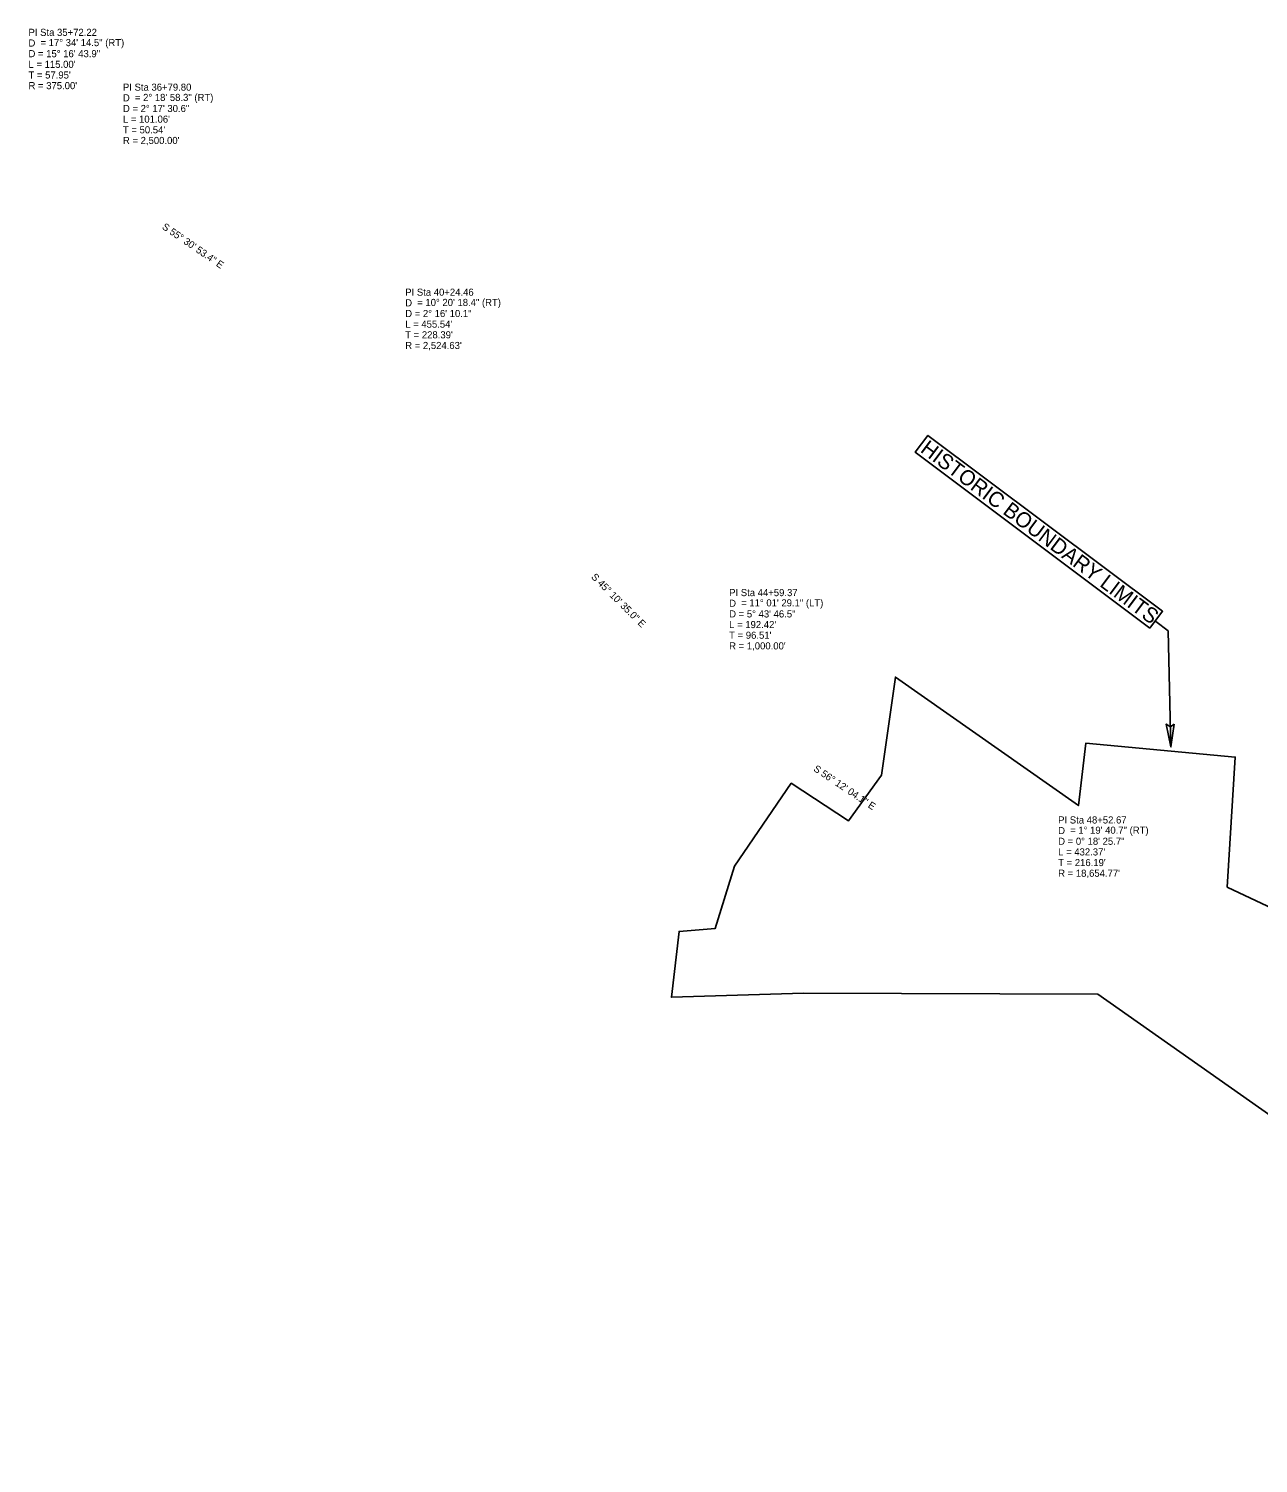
# Model space of a CAD drawing. Extents: x 928111 to 937215, y 684220 to 686530.
# Drawn here: x 930389 to 931600, y 684346 to 685759 of the extents above; entities that cross this region are included whole.
import ezdxf

# ---------------------------------------------------------------- set-up
doc = ezdxf.new("R2010")
doc.units = 0
for name, color, linetype in [('Default', 7, 'Continuous'), ('Exist Boundary Study Area', 7, 'Continuous'), ('Exist Horizontal Alignment Curve and Spiral Data', 7, 'Continuous'), ('Exist Horizontal Alignment Direction Label', 7, 'Continuous'), ('Prop DSN Text', 7, 'Continuous'), ('Prop Terminator CELL', 7, 'Continuous')]:
    doc.layers.add(name, color=color, linetype=linetype)

msp = doc.modelspace()

# ---------------------------------------------------------------- linework, layer by layer
at = {"layer": 'Default'}
for p in [(931499.2, 685174.9), (931514, 685051.5)]:
    msp.add_line(p, (931511.2, 685165.9), dxfattribs=at)
at = {"layer": 'Exist Boundary Study Area'}
msp.add_line((931442, 684808), (931152.3, 684808.7), dxfattribs=at)
for points in [[(931152.3, 684808.7), (931022.2, 684804.8), (931029.7, 684869.7), (931065.2, 684872.4), (931084.2, 684934.1), (931140.1, 685015.7), (931196.4, 684978.6), (931229.1, 685023.5), (931242.7, 685120.3), (931423, 684993.6), (931430.3, 685055.2), (931577.4, 685041.4), (931569.5, 684913.3)], [(931569.5, 684913.3), (931710.3, 684847), (931702.7, 684740.2), (931829.1, 684705.8), (931835.5, 684743.3), (931898.9, 684732.5), (931896.5, 684661.1), (932099.1, 684574.6), (932098.6, 684568.5), (932142, 684565.5), (932141, 684450.3), (932064.1, 684481.2), (932004.9, 684345.6), (931868, 684395.4), (931860.2, 684382.6), (931798.1, 684423.5), (931808.3, 684438.3), (931798.3, 684445.3), (931851.3, 684519.9), (931442, 684808)]]:
    msp.add_lwpolyline(points, dxfattribs=at)
at = {"layer": 'Prop DSN Text'}
msp.add_lwpolyline([(931493.4, 685168.6), (931262.3, 685341.8), (931274.7, 685358.4), (931505.8, 685185.2)], close=True, dxfattribs=at)
at = {"layer": 'Prop Terminator CELL'}
msp.add_lwpolyline([(931517.3, 685074), (931514, 685051.5), (931509.5, 685074), (931513.5, 685071.2)], close=True, dxfattribs=at)

# ---------------------------------------------------------------- texts
at = {"layer": 'Exist Horizontal Alignment Curve and Spiral Data'}
for s, p in [('PI Sta 35+72.22', (930389, 685752)), ('D', (930389, 685741.5)), ('= 17%%d 34\' 14.5" (RT)', (930400.8, 685741.9)), ('D = 15%%d 16\' 43.9"', (930389, 685731)), ("L = 115.00'", (930389, 685720.5)), ("T = 57.95'", (930389, 685710)), ("R = 375.00'", (930389, 685699.5)), ('PI Sta 36+79.80', (930482, 685698)), ('D', (930482, 685687.5)), ('= 2%%d 18\' 58.3" (RT)', (930493.8, 685687.9)), ('D = 2%%d 17\' 30.6"', (930482, 685677)), ("L = 101.06'", (930482, 685666.5)), ("T = 50.54'", (930482, 685656)), ("R = 2,500.00'", (930482, 685645.5)), ('PI Sta 40+24.46', (930760, 685496)), ('D', (930760, 685485.5)), ('D = 2%%d 16\' 10.1"', (930760, 685475)), ('= 10%%d 20\' 18.4" (RT)', (930771.8, 685485.9)), ("L = 455.54'", (930760, 685464.5)), ("T = 228.39'", (930760, 685454)), ("R = 2,524.63'", (930760, 685443.5)), ('PI Sta 44+59.37', (931079, 685200)), ('= 11%%d 01\' 29.1" (LT)', (931090.8, 685189.9)), ('D', (931079, 685189.5)), ('D = 5%%d 43\' 46.5"', (931079, 685179)), ("L = 192.42'", (931079, 685168.5)), ("T = 96.51'", (931079, 685158)), ("R = 1,000.00'", (931079, 685147.5)), ('PI Sta 48+52.67', (931403, 684976)), ('D', (931403, 684965.5)), ('= 1%%d 19\' 40.7" (RT)', (931414.8, 684965.9)), ('D = 0%%d 18\' 25.7"', (931403, 684955)), ("L = 432.37'", (931403, 684944.5)), ("T = 216.19'", (931403, 684934)), ("R = 18,654.77'", (931403, 684923.5))]:
    msp.add_text(s, height=7, dxfattribs=at).set_placement(p)
at = {"layer": 'Exist Horizontal Alignment Direction Label'}
for s, rotation, p in [('S 55%%d 30\' 53.4" E', 325.5148, (930519.9, 685562.4)), ('S 45%%d 10\' 35.0" E', 315.1764, (930942.6, 685218.3)), ('S 56%%d 12\' 04.1" E', 326.2011, (931161.4, 685028.3))]:
    msp.add_text(s, height=7, rotation=rotation, dxfattribs=at).set_placement(p)
at = {"layer": 'Prop DSN Text'}
msp.add_text('HISTORIC BOUNDARY LIMITS', height=15, rotation=323.1562, dxfattribs=at).set_placement((931266.4, 685342.7))

doc.saveas('drawing.dxf')
